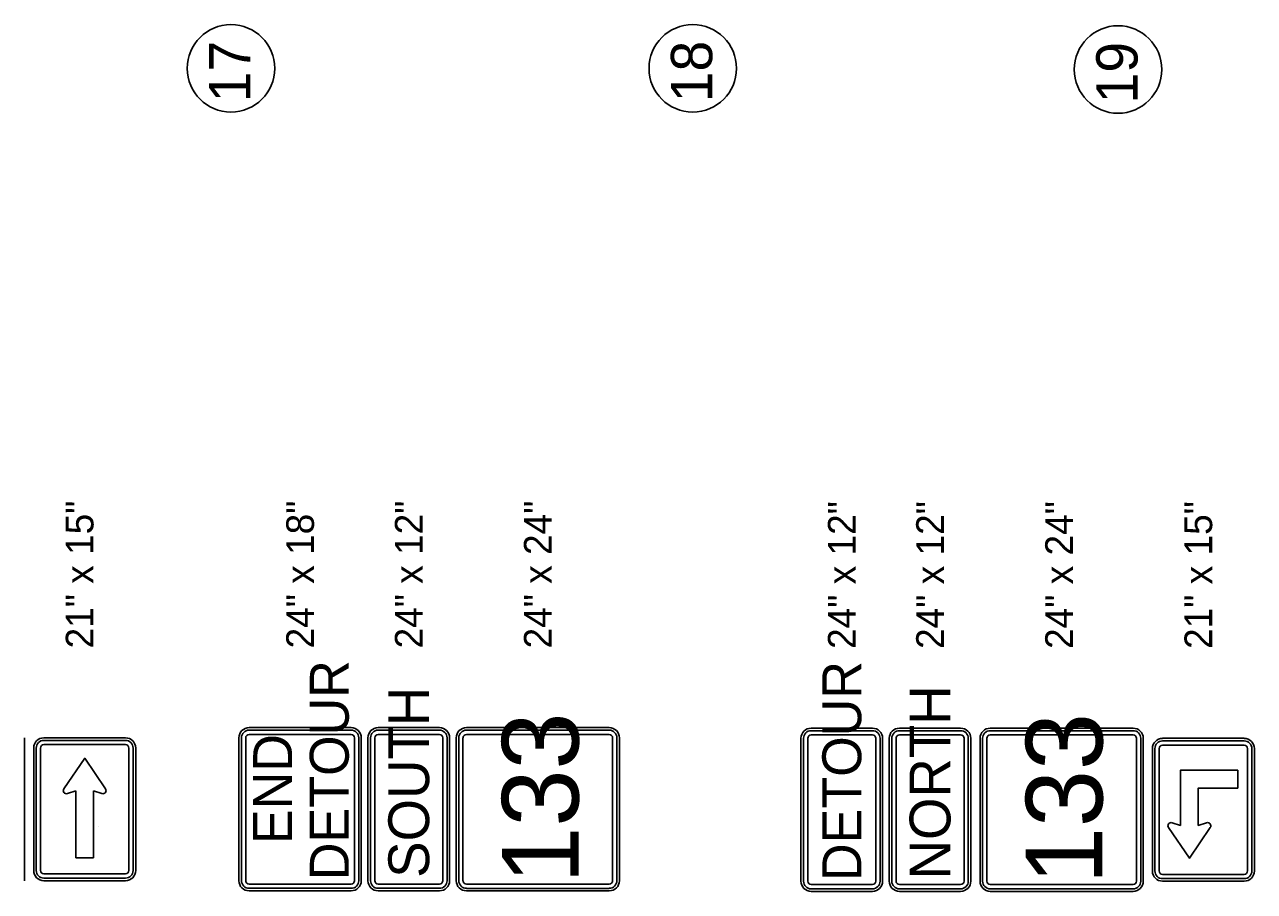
# Model space of a CAD drawing. Extents: x 1123038 to 1172987, y 554419 to 623636.
# Drawn here: x 1155641 to 1160613, y 564287 to 567791 of the extents above; entities that cross this region are included whole.
import ezdxf

# ---------------------------------------------------------------- set-up
doc = ezdxf.new("R2010")
doc.units = 0
doc.layers.add('D_Text_Standard', color=7, linetype='Continuous')
doc.layers.add('SIGNS TRAFFIC', color=7, linetype='Continuous')

msp = doc.modelspace()

# ---------------------------------------------------------------- linework, layer by layer
at = {"layer": 'D_Text_Standard'}
for centre in [(1156475, 567613.8), (1158342.2, 567613.8), (1160061.8, 567609.1)]:
    msp.add_circle(centre, 176.8, dxfattribs=at)
at = {"layer": 'SIGNS TRAFFIC'}
for p, q in [((1155687.6, 564866.3), (1155687.6, 564371.3)), ((1160546.2, 564704.4), (1160546.2, 564776.6)), ((1155813.7, 564681.8), (1155847.4, 564692.6)), ((1155847.4, 564692.6), (1155847.5, 564422.9)), ((1155919.6, 564422.9), (1155919.6, 564692.6)), ((1155919.6, 564692.6), (1155953.4, 564681.8)), ((1155847.5, 564422.9), (1155919.6, 564422.9))]:
    msp.add_line(p, q, dxfattribs=at)
for points in [[(1156548.3, 564948.8), (1156960.8, 564948.8)], [(1156548.3, 564948.8), (1156960.8, 564948.8)], [(1156548.3, 564938.5), (1156960.8, 564938.5)], [(1157070.2, 564948.8), (1157317.7, 564948.8)], [(1157070.2, 564948.8), (1157317.7, 564948.8)], [(1157070.2, 564938.5), (1157317.7, 564938.5)], [(1157427, 564948.8), (1158004.5, 564948.8)], [(1157427, 564948.8), (1158004.5, 564948.8)], [(1157427, 564938.5), (1158004.5, 564938.5)], [(1158821, 564946.7), (1159068.5, 564946.7)], [(1158821, 564946.7), (1159068.5, 564946.7)], [(1158821, 564936.4), (1159068.5, 564936.4)], [(1159177.8, 564946.7), (1159425.3, 564946.7)], [(1159177.8, 564946.7), (1159425.3, 564946.7)], [(1159177.8, 564936.4), (1159425.3, 564936.4)], [(1159545.2, 564946.7), (1160122.7, 564946.7)], [(1159545.2, 564946.7), (1160122.7, 564946.7)], [(1159545.2, 564936.4), (1160122.7, 564936.4)], [(1155640.6, 564907.6), (1155640.6, 564330.1)], [(1155640.6, 564907.6), (1155640.6, 564330.1)], [(1155718.5, 564907.6), (1156048.5, 564907.6)], [(1156048.5, 564897.2), (1155718.5, 564897.2)], [(1156507.1, 564330.1), (1156507.1, 564907.6)], [(1156507.1, 564330.1), (1156507.1, 564907.6)], [(1156517.4, 564330.1), (1156517.4, 564907.6)], [(1156534.6, 564907.6), (1156534.6, 564330.1)], [(1156960.8, 564921.3), (1156548.3, 564921.3)], [(1156974.6, 564330.1), (1156974.6, 564907.6)], [(1156991.8, 564907.6), (1156991.8, 564330.1)], [(1157002.1, 564907.6), (1157002.1, 564330.1)], [(1157002.1, 564907.6), (1157002.1, 564330.1)], [(1157028.9, 564330.1), (1157028.9, 564907.6)], [(1157028.9, 564330.1), (1157028.9, 564907.6)], [(1157039.2, 564330.1), (1157039.2, 564907.6)], [(1157056.4, 564907.6), (1157056.4, 564330.1)], [(1157317.7, 564921.3), (1157070.2, 564921.3)], [(1157331.4, 564330.1), (1157331.4, 564907.6)], [(1157348.6, 564907.6), (1157348.6, 564330.1)], [(1157358.9, 564907.6), (1157358.9, 564330.1)], [(1157358.9, 564907.6), (1157358.9, 564330.1)], [(1157385.7, 564330.1), (1157385.7, 564907.6)], [(1157385.7, 564330.1), (1157385.7, 564907.6)], [(1157396, 564330.1), (1157396, 564907.6)], [(1157413.2, 564907.6), (1157413.2, 564330.1)], [(1158004.5, 564921.3), (1157427, 564921.3)], [(1158018.2, 564330.1), (1158018.2, 564907.6)], [(1158035.4, 564907.6), (1158035.4, 564330.1)], [(1158045.7, 564907.6), (1158045.7, 564330.1)], [(1158045.7, 564907.6), (1158045.7, 564330.1)], [(1158779.8, 564328), (1158779.8, 564905.5)], [(1158779.8, 564328), (1158779.8, 564905.5)], [(1158790.1, 564328), (1158790.1, 564905.5)], [(1158807.3, 564905.5), (1158807.3, 564328)], [(1159068.5, 564919.2), (1158821, 564919.2)], [(1159082.3, 564328), (1159082.3, 564905.5)], [(1159099.5, 564905.5), (1159099.5, 564328)], [(1159109.8, 564905.5), (1159109.8, 564328)], [(1159109.8, 564905.5), (1159109.8, 564328)], [(1159136.6, 564328), (1159136.6, 564905.5)], [(1159136.6, 564328), (1159136.6, 564905.5)], [(1159146.9, 564328), (1159146.9, 564905.5)], [(1159164.1, 564905.5), (1159164.1, 564328)], [(1159425.3, 564919.2), (1159177.8, 564919.2)], [(1159439.1, 564328), (1159439.1, 564905.5)], [(1159456.3, 564905.5), (1159456.3, 564328)], [(1159466.6, 564905.5), (1159466.6, 564328)], [(1159466.6, 564905.5), (1159466.6, 564328)], [(1159503.9, 564328), (1159503.9, 564905.5)], [(1159503.9, 564328), (1159503.9, 564905.5)], [(1159514.3, 564328), (1159514.3, 564905.5)], [(1159531.4, 564905.5), (1159531.4, 564328)], [(1160122.7, 564919.2), (1159545.2, 564919.2)], [(1160136.4, 564328), (1160136.4, 564905.5)], [(1160153.6, 564905.5), (1160153.6, 564328)], [(1160163.9, 564905.5), (1160163.9, 564328)], [(1160163.9, 564905.5), (1160163.9, 564328)], [(1160241.9, 564905.5), (1160571.9, 564905.5)], [(1160571.9, 564905.5), (1160241.9, 564905.5)], [(1160571.9, 564895.2), (1160241.9, 564895.2)], [(1155677.3, 564371.3), (1155677.3, 564866.3)], [(1155704.8, 564371.3), (1155704.8, 564866.3)], [(1155718.5, 564880.1), (1156048.5, 564880.1)], [(1156062.3, 564866.3), (1156062.3, 564371.3)], [(1156079.5, 564371.3), (1156079.5, 564866.3)], [(1156089.8, 564866.3), (1156089.8, 564371.3)], [(1160200.7, 564369.2), (1160200.7, 564864.2)], [(1160200.7, 564864.2), (1160200.7, 564369.2)], [(1160211, 564864.2), (1160211, 564369.2)], [(1160228.2, 564369.2), (1160228.2, 564864.2)], [(1160241.9, 564878), (1160571.9, 564878)], [(1160585.6, 564864.2), (1160585.6, 564369.2)], [(1160602.8, 564369.2), (1160602.8, 564864.2)], [(1160613.2, 564864.2), (1160613.2, 564369.2)], [(1160613.2, 564369.2), (1160613.2, 564864.2)], [(1155968, 564701.4), (1155883.5, 564825.1), (1155799.1, 564701.4)], [(1160546.2, 564776.6), (1160314.1, 564776.6), (1160314.2, 564553.4), (1160280.4, 564564.2)], [(1160420.1, 564564.2), (1160386.3, 564553.4), (1160386.3, 564704.4), (1160546.2, 564704.4)], [(1155941.4, 564548.7), (1155941.3, 564548.8)], [(1160265.8, 564544.6), (1160350.2, 564420.9), (1160434.7, 564544.6)], [(1156048.5, 564357.6), (1155718.5, 564357.6)], [(1155718.5, 564340.4), (1156048.5, 564340.4)], [(1160571.9, 564355.5), (1160241.9, 564355.5)], [(1160241.9, 564338.3), (1160571.9, 564338.3)], [(1156048.5, 564330.1), (1155718.5, 564330.1)], [(1156548.3, 564316.3), (1156960.8, 564316.3)], [(1156960.8, 564299.2), (1156548.3, 564299.2)], [(1156960.8, 564288.8), (1156548.3, 564288.8)], [(1156960.8, 564288.8), (1156548.3, 564288.8)], [(1157070.2, 564316.3), (1157317.7, 564316.3)], [(1157317.7, 564299.2), (1157070.2, 564299.2)], [(1157317.7, 564288.8), (1157070.2, 564288.8)], [(1157317.7, 564288.8), (1157070.2, 564288.8)], [(1157427, 564316.3), (1158004.5, 564316.3)], [(1158004.5, 564299.1), (1157427, 564299.1)], [(1158004.5, 564288.8), (1157427, 564288.8)], [(1158004.5, 564288.8), (1157427, 564288.8)], [(1158821, 564314.2), (1159068.5, 564314.2)], [(1159068.5, 564297.1), (1158821, 564297.1)], [(1159177.8, 564314.2), (1159425.3, 564314.2)], [(1159425.3, 564297.1), (1159177.8, 564297.1)], [(1159545.2, 564314.2), (1160122.7, 564314.2)], [(1160122.7, 564297), (1159545.2, 564297)], [(1160571.9, 564328), (1160241.9, 564328)], [(1160241.9, 564328), (1160571.9, 564328)], [(1159068.5, 564286.7), (1158821, 564286.7)], [(1159068.5, 564286.7), (1158821, 564286.7)], [(1159425.3, 564286.7), (1159177.8, 564286.7)], [(1159425.3, 564286.7), (1159177.8, 564286.7)], [(1160122.7, 564286.7), (1159545.2, 564286.7)], [(1160122.7, 564286.7), (1159545.2, 564286.7)]]:
    msp.add_lwpolyline(points, dxfattribs=at)
for centre, radius, start, end in [((1156548.3, 564907.6), 41.2, 90, 180), ((1156548.3, 564907.6), 41.2, 90, 180), ((1156548.3, 564907.6), 30.9, 90, 180), ((1156960.8, 564907.6), 41.2, 360, 90), ((1156960.8, 564907.6), 41.2, 360, 90), ((1156960.8, 564907.6), 30.9, 360, 90), ((1157070.2, 564907.6), 41.2, 90, 180), ((1157070.2, 564907.6), 41.2, 90, 180), ((1157070.2, 564907.6), 30.9, 90, 180), ((1157317.7, 564907.6), 41.2, 360, 90), ((1157317.7, 564907.6), 41.2, 360, 90), ((1157317.7, 564907.6), 30.9, 360, 90), ((1157427, 564907.6), 41.2, 90, 180), ((1157427, 564907.6), 41.2, 90, 180), ((1157427, 564907.6), 30.9, 90, 180), ((1158004.5, 564907.6), 41.2, 360, 90), ((1158004.5, 564907.6), 41.2, 360, 90), ((1158004.5, 564907.6), 30.9, 360, 90), ((1158821, 564905.5), 41.2, 90, 180), ((1158821, 564905.5), 41.2, 90, 180), ((1158821, 564905.5), 30.9, 90, 180), ((1159068.5, 564905.5), 41.2, 360, 90), ((1159068.5, 564905.5), 41.2, 360, 90), ((1159068.5, 564905.5), 30.9, 360, 90), ((1159177.8, 564905.5), 41.2, 90, 180), ((1159177.8, 564905.5), 41.2, 90, 180), ((1159177.8, 564905.5), 30.9, 90, 180), ((1159425.3, 564905.5), 41.2, 360, 90), ((1159425.3, 564905.5), 41.2, 360, 90), ((1159425.3, 564905.5), 30.9, 360, 90), ((1159545.2, 564905.5), 41.2, 90, 180), ((1159545.2, 564905.5), 41.2, 90, 180), ((1159545.2, 564905.5), 30.9, 90, 180), ((1160122.7, 564905.5), 41.2, 360, 90), ((1160122.7, 564905.5), 41.2, 360, 90), ((1160122.7, 564905.5), 30.9, 360, 90), ((1155718.5, 564866.3), 41.2, 90, 180), ((1155718.5, 564866.3), 30.9, 90, 180), ((1156048.5, 564866.3), 41.2, 360, 90), ((1156048.5, 564866.3), 30.9, 360, 90), ((1156548.3, 564907.6), 13.7, 90, 180), ((1156960.8, 564907.6), 13.7, 360, 90), ((1157070.2, 564907.6), 13.7, 90, 180), ((1157317.7, 564907.6), 13.7, 360, 90), ((1157427, 564907.6), 13.7, 90, 180), ((1158004.5, 564907.6), 13.7, 360, 90), ((1158821, 564905.5), 13.7, 90, 180), ((1159068.5, 564905.5), 13.7, 360, 90), ((1159177.8, 564905.5), 13.7, 90, 180), ((1159425.3, 564905.5), 13.7, 360, 90), ((1159545.2, 564905.5), 13.7, 90, 180), ((1160122.7, 564905.5), 13.7, 360, 90), ((1160241.9, 564864.2), 41.2, 90, 180), ((1160241.9, 564864.2), 41.2, 90, 180), ((1160241.9, 564864.2), 30.9, 90, 180), ((1160571.9, 564864.2), 41.2, 360, 90), ((1160571.9, 564864.2), 41.2, 360, 90), ((1160571.9, 564864.2), 30.9, 360, 90), ((1155718.5, 564866.3), 13.7, 90, 180), ((1156048.5, 564866.3), 13.7, 360, 90), ((1160241.9, 564864.2), 13.7, 90, 180), ((1160571.9, 564864.2), 13.7, 360, 90), ((1155809.7, 564694.1), 12.9, 145.6763, 287.8128), ((1155957.3, 564694.1), 12.9, 252.1872, 34.3237), ((1160276.4, 564551.9), 12.9, 72.1872, 214.3237), ((1160424, 564551.9), 12.9, 325.6763, 107.8128), ((1155718.5, 564371.3), 41.2, 180, 270), ((1155718.5, 564371.3), 30.9, 180, 270), ((1155718.5, 564371.3), 13.7, 180, 270), ((1156048.5, 564371.3), 41.2, 270, 0), ((1156048.5, 564371.3), 30.9, 270, 0), ((1156048.5, 564371.3), 13.7, 270, 0), ((1160241.9, 564369.2), 41.2, 180, 270), ((1160241.9, 564369.2), 41.2, 180, 270), ((1160241.9, 564369.2), 30.9, 180, 270), ((1160241.9, 564369.2), 13.7, 180, 270), ((1160571.9, 564369.2), 41.2, 270, 0), ((1160571.9, 564369.2), 41.2, 270, 0), ((1160571.9, 564369.2), 30.9, 270, 0), ((1160571.9, 564369.2), 13.7, 270, 0), ((1156548.3, 564330.1), 41.2, 180, 270), ((1156548.3, 564330.1), 41.2, 180, 270), ((1156548.3, 564330.1), 30.9, 180, 270), ((1156548.3, 564330.1), 13.7, 180, 270), ((1156960.8, 564330.1), 41.2, 270, 360), ((1156960.8, 564330.1), 41.2, 270, 360), ((1156960.8, 564330.1), 30.9, 270, 360), ((1156960.8, 564330.1), 13.7, 270, 360), ((1157070.2, 564330.1), 41.2, 180, 270), ((1157070.2, 564330.1), 41.2, 180, 270), ((1157070.2, 564330.1), 30.9, 180, 270), ((1157070.2, 564330.1), 13.7, 180, 270), ((1157317.7, 564330.1), 41.2, 270, 360), ((1157317.7, 564330.1), 41.2, 270, 360), ((1157317.7, 564330.1), 30.9, 270, 360), ((1157317.7, 564330.1), 13.7, 270, 360), ((1157427, 564330.1), 41.2, 180, 270), ((1157427, 564330.1), 41.2, 180, 270), ((1157427, 564330.1), 30.9, 180, 270), ((1157427, 564330.1), 13.7, 180, 270), ((1158004.5, 564330.1), 41.2, 270, 360), ((1158004.5, 564330.1), 41.2, 270, 360), ((1158004.5, 564330.1), 30.9, 270, 360), ((1158004.5, 564330.1), 13.7, 270, 360), ((1158821, 564328), 41.2, 180, 270), ((1158821, 564328), 41.2, 180, 270), ((1158821, 564328), 30.9, 180, 270), ((1158821, 564328), 13.7, 180, 270), ((1159068.5, 564328), 41.2, 270, 360), ((1159068.5, 564328), 41.2, 270, 360), ((1159068.5, 564328), 30.9, 270, 360), ((1159068.5, 564328), 13.7, 270, 360), ((1159177.8, 564328), 41.2, 180, 270), ((1159177.8, 564328), 41.2, 180, 270), ((1159177.8, 564328), 30.9, 180, 270), ((1159177.8, 564328), 13.7, 180, 270), ((1159425.3, 564328), 41.2, 270, 360), ((1159425.3, 564328), 41.2, 270, 360), ((1159425.3, 564328), 30.9, 270, 360), ((1159425.3, 564328), 13.7, 270, 360), ((1159545.2, 564328), 41.2, 180, 270), ((1159545.2, 564328), 41.2, 180, 270), ((1159545.2, 564328), 30.9, 180, 270), ((1159545.2, 564328), 13.7, 180, 270), ((1160122.7, 564328), 41.2, 270, 360), ((1160122.7, 564328), 41.2, 270, 360), ((1160122.7, 564328), 30.9, 270, 360), ((1160122.7, 564328), 13.7, 270, 360)]:
    msp.add_arc(centre, radius, start, end, dxfattribs=at)

# ---------------------------------------------------------------- texts
at = {"layer": 'D_Text_Standard'}
for s, height, p in [('17', 167.06, (1156553.8, 567476.8)), ('18', 167.06, (1158421, 567476.8)), ('19', 167.06, (1160140.6, 567472.1)), ('21" x 15"', 111.99, (1155919.1, 565268.8)), ('24" x 18"', 111.99, (1156810.6, 565268.8)), ('24" x 12"', 111.99, (1157249.9, 565268.8)), ('24" x 24"', 111.99, (1157771.7, 565268.8)), ('24" x 12"', 111.99, (1159000.8, 565266.7)), ('24" x 12"', 111.99, (1159357.6, 565266.7)), ('24" x 24"', 111.99, (1159879.4, 565266.7)), ('21" x 15"', 111.99, (1160442.4, 565266.7))]:
    msp.add_text(s, height=height, rotation=90, dxfattribs=at).set_placement(p)
at = {"layer": 'SIGNS TRAFFIC'}
for s, height, p in [('DETOUR', 157.5, (1156951.2, 564332.2)), ('DETOUR', 157.5, (1159023.6, 564328.7)), ('SOUTH', 165, (1157276.4, 564341.6)), ('NORTH', 165, (1159384.1, 564335.1)), ('133', 310, (1157880.7, 564318.2)), ('133', 310, (1159998.9, 564316.1)), ('END', 157.5, (1156722.2, 564478.1))]:
    msp.add_text(s, height=height, rotation=90, dxfattribs=at).set_placement(p)

doc.saveas('drawing.dxf')
